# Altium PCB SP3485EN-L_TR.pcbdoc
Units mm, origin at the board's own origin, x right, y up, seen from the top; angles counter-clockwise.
Board outline 17.7 x 20.06 mm, 2 copper layers (Top Layer, Bottom Layer), stack 0 mm thick; 1 components, 0 nets, 8 pads, 0 vias.
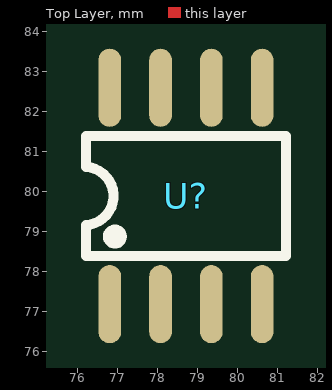
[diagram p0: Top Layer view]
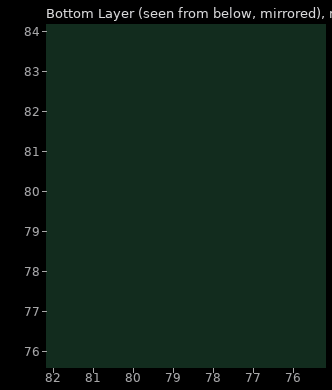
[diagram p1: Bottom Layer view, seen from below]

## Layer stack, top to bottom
Top Layer: signal copper (thickness not stored)
Bottom Layer: signal copper (thickness not stored)

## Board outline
87.551,69.85 69.85,69.85 69.85,89.911 87.551,89.911

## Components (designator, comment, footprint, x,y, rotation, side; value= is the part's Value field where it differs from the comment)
U? "SP3485EN-L/TR" SOIC-8_L5.0-W4.0-P1.27-LS6.0-BL 78.699,79.88 r0 top

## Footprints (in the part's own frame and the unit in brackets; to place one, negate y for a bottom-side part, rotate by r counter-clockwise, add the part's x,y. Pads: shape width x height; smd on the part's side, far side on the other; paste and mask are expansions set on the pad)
SOIC-8_L5.0-W4.0-P1.27-LS6.0-BL [mil]
  oval 22.4x76.8 smd: 1(-75,-106.5) 2(-25,-106.5) 3(25,-106.5) 4(75,-106.5) 5(75,106.5) 6(25,106.5) 7(-25,106.5) 8(-75,106.5)
  silkscreen extent -98,-59 98,59

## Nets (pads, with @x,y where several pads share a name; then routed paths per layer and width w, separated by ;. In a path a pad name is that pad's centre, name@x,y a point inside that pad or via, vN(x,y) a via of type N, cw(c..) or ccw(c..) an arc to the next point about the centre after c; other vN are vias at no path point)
pads on no net: U?.1 U?.2 U?.3 U?.4 U?.5 U?.6 U?.7 U?.8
